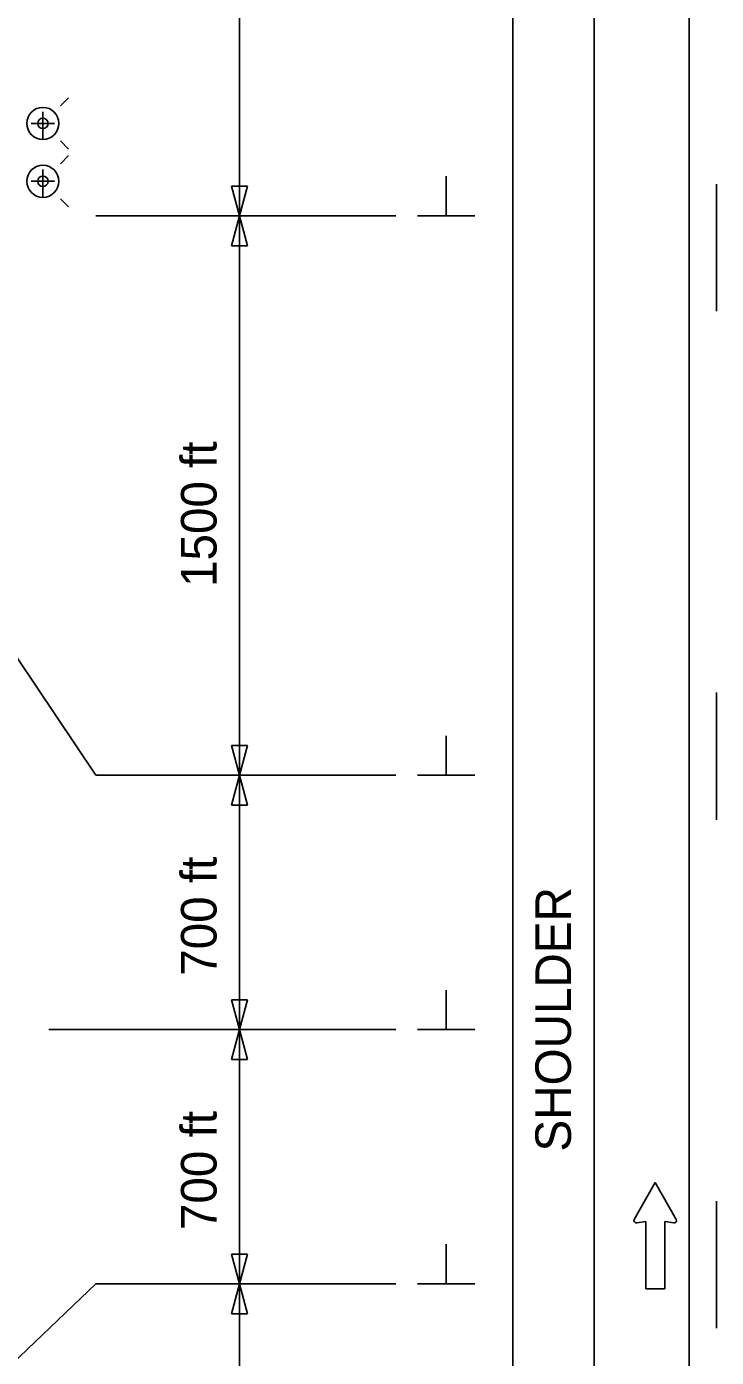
# Model space of a CAD drawing. Extents: x 15277 to 18126, y 1908 to 6555.
# Drawn here: x 16480.8 to 16616.4, y 2534 to 2795.7 of the extents above; entities that cross this region are included whole.
import ezdxf

# ---------------------------------------------------------------- set-up
doc = ezdxf.new("R2010")
doc.units = 0
for name, color, linetype in [('ALI_LEGAL_EX', 7, 'Continuous'), ('MT_SCRATCH_LEVEL_E', 7, 'Continuous'), ('PAVT_EDGE_EX', 7, 'Continuous'), ('TRAFFIC_SIGNS_PR', 7, 'Continuous'), ('TYPICAL_TEXT_DIMEN_PR', 7, 'Continuous')]:
    doc.layers.add(name, color=color, linetype=linetype)

msp = doc.modelspace()

# ---------------------------------------------------------------- linework, layer by layer
at = {"layer": 'ALI_LEGAL_EX'}
msp.add_line((16610.98, 3236.46), (16610.98, 2407.28), dxfattribs=at)
for points in [[(16616.35, 2764.74), (16616.35, 2739.74)], [(16616.35, 2664.74), (16616.35, 2639.74)], [(16616.35, 2539.74), (16616.35, 2564.74)], [(16616.35, 2539.74), (16616.35, 2564.74)]]:
    msp.add_lwpolyline(points, dxfattribs=at)
at = {"layer": 'MT_SCRATCH_LEVEL_E'}
for p, q in [((16604.32, 2568.38), (16600.21, 2561.14)), ((16608.47, 2561.14), (16604.32, 2568.38)), ((16600.69, 2560.45), (16602.47, 2560.77)), ((16602.47, 2560.77), (16602.47, 2547.51)), ((16606.21, 2547.51), (16606.21, 2560.77)), ((16606.21, 2560.77), (16607.99, 2560.45)), ((16602.47, 2547.51), (16606.21, 2547.51))]:
    msp.add_line(p, q, dxfattribs=at)
for centre, start, end in [((16600.62, 2560.91), 150.4248, 279.9638), ((16608.06, 2560.91), 260.0362, 29.7731)]:
    msp.add_arc(centre, 0.463, start, end, dxfattribs=at)
at = {"layer": 'PAVT_EDGE_EX'}
for p, q in [((16576.35, 3138.78), (16576.35, 2305.55)), ((16592.35, 3138.78), (16592.35, 2305.55))]:
    msp.add_line(p, q, dxfattribs=at)
at = {"layer": 'TRAFFIC_SIGNS_PR'}
for p, q in [((16487.39, 2780.1), (16489.02, 2781.72)), ((16483.96, 2776.67), (16481.66, 2776.67)), ((16483.96, 2776.67), (16483.96, 2778.97)), ((16483.96, 2776.67), (16483.96, 2773.52)), ((16483.96, 2776.67), (16486.27, 2776.67)), ((16489.01, 2771.62), (16487.39, 2773.25)), ((16487.39, 2768.7), (16489.02, 2770.33)), ((16483.96, 2765.28), (16483.96, 2767.58)), ((16483.96, 2765.28), (16481.66, 2765.28)), ((16483.96, 2765.28), (16483.96, 2762.13)), ((16483.96, 2765.28), (16486.27, 2765.28)), ((16489.01, 2760.23), (16487.39, 2761.86))]:
    msp.add_line(p, q, dxfattribs=at)
for centre, radius in [((16483.96, 2776.67), 3.15), ((16483.96, 2776.67), 1.02), ((16483.96, 2765.28), 3.15), ((16483.96, 2765.28), 1.02)]:
    msp.add_circle(centre, radius, dxfattribs=at)
at = {"layer": 'TYPICAL_TEXT_DIMEN_PR'}
for p, q in [((16522.62, 2868.48), (16522.62, 2758.48)), ((16563.23, 2758.48), (16563.23, 2766.26)), ((16522.62, 2758.48), (16521.06, 2764.34)), ((16521.06, 2764.34), (16522.62, 2764.34)), ((16522.62, 2764.34), (16524.19, 2764.34)), ((16524.19, 2764.34), (16522.62, 2758.48)), ((16494.38, 2758.48), (16553.35, 2758.48)), ((16521.06, 2752.61), (16522.62, 2758.48)), ((16521.06, 2752.61), (16522.62, 2758.48)), ((16522.62, 2758.48), (16522.62, 2648.48)), ((16522.62, 2758.48), (16524.19, 2752.61)), ((16522.62, 2758.48), (16524.19, 2752.61)), ((16557.6, 2758.48), (16568.85, 2758.48)), ((16522.62, 2752.61), (16521.06, 2752.61)), ((16522.62, 2752.61), (16521.06, 2752.61)), ((16524.19, 2752.61), (16522.62, 2752.61)), ((16524.19, 2752.61), (16522.62, 2752.61)), ((16494.38, 2648.48), (16459.72, 2700.07)), ((16563.23, 2648.48), (16563.23, 2656.26)), ((16522.62, 2648.48), (16521.06, 2654.34)), ((16521.06, 2654.34), (16522.62, 2654.34)), ((16522.62, 2648.48), (16521.06, 2654.34)), ((16521.06, 2654.34), (16522.62, 2654.34)), ((16522.62, 2654.34), (16524.19, 2654.34)), ((16524.19, 2654.34), (16522.62, 2648.48)), ((16522.62, 2654.34), (16524.19, 2654.34)), ((16524.19, 2654.34), (16522.62, 2648.48)), ((16494.38, 2648.48), (16553.35, 2648.48)), ((16521.05, 2642.61), (16522.62, 2648.48)), ((16522.62, 2648.48), (16522.62, 2598.48)), ((16522.62, 2648.48), (16524.2, 2642.61)), ((16557.6, 2648.48), (16568.85, 2648.48)), ((16522.62, 2642.61), (16521.05, 2642.61)), ((16524.2, 2642.61), (16522.62, 2642.61)), ((16522.62, 2598.48), (16521.05, 2604.34)), ((16521.05, 2604.34), (16522.62, 2604.34)), ((16522.62, 2604.34), (16524.2, 2604.34)), ((16524.2, 2604.34), (16522.62, 2598.48)), ((16563.23, 2598.48), (16563.23, 2606.26)), ((16485.14, 2598.48), (16553.35, 2598.48)), ((16521.05, 2592.61), (16522.62, 2598.48)), ((16522.62, 2598.48), (16522.62, 2548.48)), ((16522.62, 2598.48), (16524.2, 2592.61)), ((16557.6, 2598.48), (16568.85, 2598.48)), ((16522.62, 2592.61), (16521.05, 2592.61)), ((16524.2, 2592.61), (16522.62, 2592.61)), ((16522.62, 2548.48), (16521.05, 2554.34)), ((16521.05, 2554.34), (16522.62, 2554.34)), ((16522.62, 2554.34), (16524.2, 2554.34)), ((16524.2, 2554.34), (16522.62, 2548.48)), ((16563.23, 2548.48), (16563.23, 2556.26)), ((16494.38, 2548.48), (16432.89, 2489.71)), ((16494.38, 2548.48), (16553.35, 2548.48)), ((16521.05, 2542.61), (16522.62, 2548.48)), ((16522.62, 2548.48), (16522.62, 2498.48)), ((16522.62, 2548.48), (16524.2, 2542.61)), ((16557.6, 2548.48), (16568.85, 2548.48)), ((16522.62, 2542.61), (16521.05, 2542.61)), ((16524.2, 2542.61), (16522.62, 2542.61))]:
    msp.add_line(p, q, dxfattribs=at)

# ---------------------------------------------------------------- texts
for s, p in [('1500 ft', (16518.1, 2685.51)), ('700 ft', (16518.1, 2609.05)), ('SHOULDER', (16587.77, 2574.49)), ('700 ft', (16518.1, 2559.05))]:
    msp.add_text(s, height=7, rotation=90, dxfattribs=at).set_placement(p)

doc.saveas('drawing.dxf')
